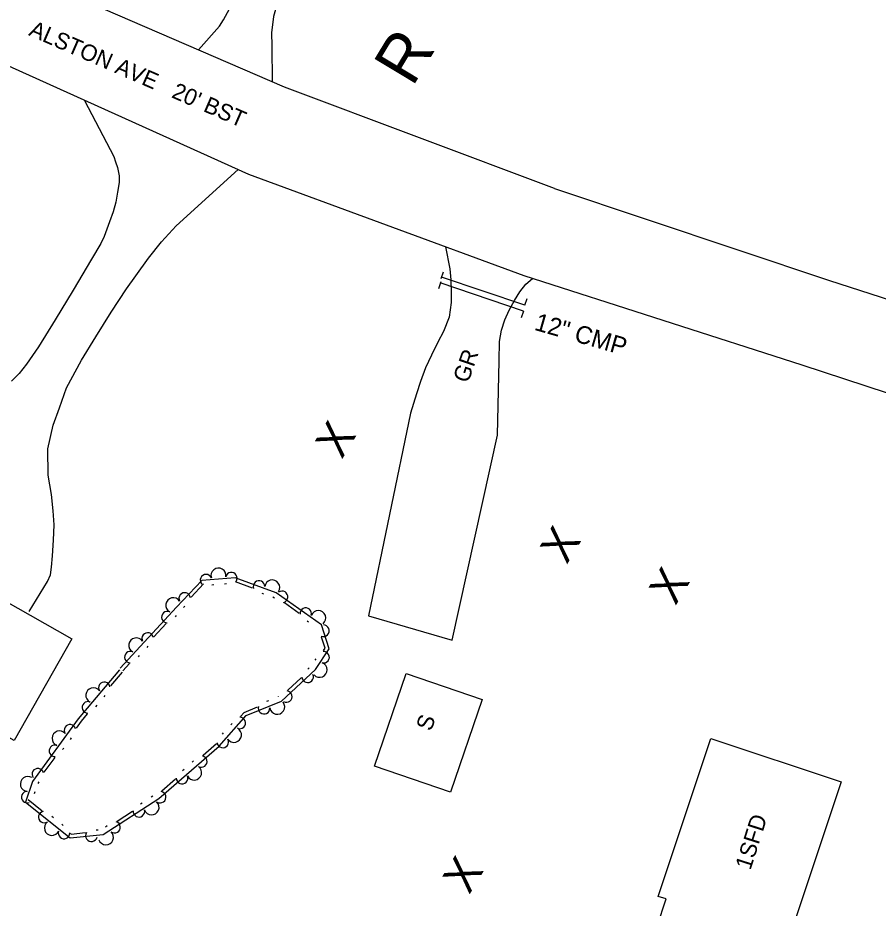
# Model space of a CAD drawing. Extents: x 2030130 to 2036320, y 723205 to 762423.
# Drawn here: x 2032711.6 to 2032905.6, y 760450.9 to 760651.9 of the extents above; entities that cross this region are included whole.
import ezdxf

# ---------------------------------------------------------------- set-up
doc = ezdxf.new("R2010")
doc.units = 0
for name, color, linetype in [('Draft_Station Cardinal Points', 7, 'Continuous'), ('Draft_Station Labels Major', 7, 'Continuous'), ('Draft_Station Tics Major', 7, 'Continuous'), ('Draft_Station Tics Minor', 7, 'Continuous'), ('Exist Terrain Model Ground Surface', 7, 'Continuous'), ('Old_Level_23', 7, 'Continuous'), ('Old_Level_26', 7, 'Continuous'), ('Old_Level_28', 7, 'Continuous')]:
    doc.layers.add(name, color=color, linetype=linetype)

msp = doc.modelspace()

# ---------------------------------------------------------------- linework, layer by layer
at = {"layer": 'Draft_Station Labels Major'}
for points in [[(2032752.34, 760644.62), (2032757.03, 760649.97), (2032757.96, 760651.43), (2032760.11, 760655.38), (2032761.37, 760659.07), (2032762.73, 760664.47), (2032770.18, 760709.31), (2032771.53, 760735.41)], [(2032780.04, 760733.35), (2032779.16, 760708.37), (2032776.48, 760684.96), (2032775.31, 760677.51), (2032774.46, 760672.51), (2032773.6, 760667.55), (2032772.54, 760662.87), (2032770.43, 760656.46), (2032769.22, 760652.17), (2032768.74, 760648.45), (2032768.83, 760645.51), (2032768.92, 760637.43)], [(2032832.59, 760613.36), (2032771.69, 760636.24), (2032711.99, 760662.1)], [(2032825.76, 760593.66), (2032763.66, 760616.53), (2032703.33, 760643.73), (2032699.59, 760645.59)], [(2032726.62, 760633.23), (2032733.21, 760620.6), (2032733.62, 760619.35), (2032734.05, 760618.08), (2032734.3, 760616.94), (2032734.41, 760616.17), (2032734.39, 760614.69), (2032734.07, 760612.53), (2032733.65, 760610.24), (2032733.06, 760608.08), (2032732.28, 760605.84), (2032731.02, 760602.53), (2032730.27, 760600.96), (2032728.2, 760597.39), (2032724.07, 760590.43), (2032719.97, 760583.71), (2032716.25, 760577.65), (2032713.53, 760573.73), (2032711.84, 760571.59), (2032710.16, 760569.86)], [(2032714.12, 760517.87), (2032718.27, 760524.7), (2032718.92, 760526.17), (2032719.16, 760527.93), (2032719.42, 760530.43), (2032719.62, 760534.02), (2032719.79, 760537.49), (2032719.55, 760540.64), (2032719.15, 760544.27), (2032718.4, 760548.66), (2032718.32, 760554.57), (2032719.55, 760559.95), (2032721, 760563.82), (2032722.56, 760568.39), (2032725.95, 760574.6), (2032729.13, 760579.86), (2032732.59, 760585.48), (2032736.08, 760590.7), (2032738.16, 760593.62), (2032741.04, 760597.62), (2032744, 760601.3), (2032747.3, 760604.91), (2032761.28, 760617.61)], [(2032832.59, 760613.36), (2032894.61, 760592.59), (2032957.05, 760572.43), (2033019.49, 760552.28)], [(2032808.03, 760600.19), (2032809, 760595.23), (2032809.25, 760592.75), (2032809.3, 760590.11), (2032809.33, 760587.59), (2032808.81, 760584.29), (2032807.53, 760581.09), (2032806.3, 760578.65), (2032804.83, 760575.77), (2032803.51, 760572.85), (2032802.39, 760569.78), (2032801.5, 760567), (2032800.15, 760562.67), (2032790.64, 760516.94), (2032809.54, 760511.46), (2032819.73, 760557.72), (2032820.12, 760574.49), (2032820.23, 760578.8), (2032820.67, 760581.4), (2032821.37, 760583.69), (2032822.35, 760585.87), (2032823.55, 760588.1), (2032824.78, 760590.03), (2032826.14, 760591.76), (2032827.6, 760593.07)], [(2033013.2, 760532.89), (2032950.76, 760553.04), (2032888.41, 760573.49), (2032825.76, 760593.66)]]:
    msp.add_lwpolyline(points, dxfattribs=at)
at = {"layer": 'Draft_Station Tics Major'}
for points in [[(2032734.47, 760504.77), (2032725.2, 760493.64), (2032714.87, 760479.52), (2032713.33, 760474.89), (2032723.35, 760466.83), (2032730.83, 760467.54), (2032743.34, 760475.72), (2032756.96, 760487.5), (2032763.08, 760494.42), (2032771.02, 760497.68), (2032778.68, 760504.78), (2032781.78, 760509.48), (2032780.04, 760514.92), (2032769.82, 760522.14), (2032760.55, 760525.5), (2032753.06, 760524.9), (2032747.34, 760518.87), (2032734.65, 760505.09)], [(2032753.47, 760524.14), (2032750.65, 760521.16)], [(2032755.75, 760523.88), (2032755.34, 760523.84)], [(2032758.62, 760524.11), (2032758.21, 760524.07)], [(2032764.52, 760523.19), (2032760.67, 760524.58)], [(2032767.08, 760521.82), (2032766.7, 760521.96)], [(2032769.44, 760520.9), (2032769.11, 760521.14)], [(2032749.25, 760519.1), (2032748.97, 760518.8)], [(2032775.04, 760517.45), (2032771.69, 760519.82)], [(2032745.06, 760515.18), (2032742.28, 760512.16)], [(2032747.31, 760517.01), (2032747.03, 760516.71)], [(2032777.14, 760515.46), (2032776.81, 760515.7)], [(2032780.52, 760509.06), (2032780.88, 760509.6), (2032780.07, 760512.14)], [(2032740.92, 760510.07), (2032740.64, 760509.77)], [(2032738.97, 760507.96), (2032738.69, 760507.66)], [(2032778.6, 760506.89), (2032778.82, 760507.23)], [(2032736.73, 760506.13), (2032735.26, 760504.53)], [(2032776.99, 760504.89), (2032777.29, 760505.17)], [(2032735.1, 760504.24), (2032732.47, 760501.09)], [(2032772.46, 760500.14), (2032775.47, 760502.92)], [(2032731.21, 760498.94), (2032730.95, 760498.62)], [(2032767.76, 760497.67), (2032768.14, 760497.83)], [(2032770.34, 760498.73), (2032770.38, 760498.76)], [(2032729.38, 760496.73), (2032729.12, 760496.42)], [(2032761.81, 760494.22), (2032762.59, 760495.11), (2032765.64, 760496.36)], [(2032727.23, 760494.79), (2032725.85, 760493.13), (2032724.73, 760491.6)], [(2032759.6, 760492.34), (2032759.87, 760492.65)], [(2032723.61, 760489.37), (2032723.37, 760489.04)], [(2032757.7, 760490.19), (2032757.97, 760490.5)], [(2032721.91, 760487.06), (2032721.67, 760486.73)], [(2032753.35, 760485.47), (2032756.38, 760488.09)], [(2032719.89, 760484.98), (2032717.46, 760481.67)], [(2032750.91, 760483.9), (2032751.22, 760484.17)], [(2032748.74, 760482.02), (2032749.05, 760482.29)], [(2032716.34, 760479.44), (2032716.1, 760479.11)], [(2032744.04, 760477.42), (2032747.15, 760480.1)], [(2032715.39, 760477.17), (2032715.26, 760476.78)], [(2032713.89, 760475.49), (2032717.09, 760472.92)], [(2032741.64, 760476.08), (2032741.98, 760476.31)], [(2032739.24, 760474.51), (2032739.58, 760474.73)], [(2032719.26, 760471.7), (2032719.58, 760471.44)], [(2032733.97, 760470.57), (2032737.4, 760472.82)], [(2032721.49, 760469.9), (2032721.81, 760469.64)], [(2032731.34, 760469.34), (2032731.69, 760469.57)], [(2032723.47, 760467.78), (2032723.6, 760467.68), (2032726.86, 760467.99)], [(2032729.27, 760468.63), (2032729.68, 760468.66)]]:
    msp.add_lwpolyline(points, dxfattribs=at)
for centre, radius, start, end in [((2032756.82, 760526.02), 1.69, 350.5307, 198.6032), ((2032754.02, 760524.97), 1.3, 23.0019, 223.7985), ((2032759.74, 760525.43), 1.3, 325.3354, 166.132), ((2032765.96, 760523.54), 1.3, 358.5358, 199.3323), ((2032768.94, 760523.33), 1.69, 326.0646, 174.1371), ((2032749.21, 760520.84), 1.3, 7.2968, 208.0933), ((2032771.16, 760521.2), 1.3, 285.515, 126.3115), ((2032746.63, 760519.31), 1.69, 33.3291, 241.4016), ((2032745.29, 760516.64), 1.3, 65.8003, 266.5969), ((2032776.51, 760517.41), 1.3, 343.1814, 183.978), ((2032779.33, 760516.42), 1.69, 310.7103, 158.7827), ((2032740.85, 760511.81), 1.3, 8.1338, 208.9304), ((2032780.47, 760513.56), 1.3, 248.4828, 89.2793), ((2032738.3, 760510.26), 1.69, 33.3291, 241.4016), ((2032736.96, 760507.59), 1.3, 65.8003, 266.5969), ((2032780.53, 760507.58), 1.3, 255.0228, 95.8194), ((2032779.63, 760504.73), 1.69, 222.5516, 70.6241), ((2032776.93, 760503.16), 1.3, 183.5829, 24.3794), ((2032731.06, 760500.67), 1.3, 11.0049, 211.8014), ((2032728.59, 760498.99), 1.69, 36.2001, 244.2726), ((2032772.12, 760498.7), 1.3, 241.2493, 82.0459), ((2032727.38, 760496.26), 1.3, 68.6713, 269.4679), ((2032770.06, 760496.4), 1.69, 188.2658, 36.3383), ((2032767.09, 760496.07), 1.3, 163.0705, 3.8671), ((2032761.61, 760492.75), 1.3, 246.9458, 87.7424), ((2032723.34, 760491.09), 1.3, 14.5724, 215.369), ((2032760.32, 760490.06), 1.69, 214.4746, 62.5471), ((2032720.98, 760489.26), 1.69, 39.7677, 247.8402), ((2032757.8, 760488.45), 1.3, 189.2793, 30.0759), ((2032719.95, 760486.46), 1.3, 72.2389, 273.0355), ((2032752.96, 760484.04), 1.3, 239.2811, 80.0777), ((2032716.08, 760481.16), 1.3, 14.5724, 215.369), ((2032751.32, 760481.54), 1.69, 206.8099, 54.8824), ((2032713.83, 760478.99), 1.69, 57.5775, 265.65), ((2032748.61, 760480.29), 1.3, 181.6146, 22.4112), ((2032713.7, 760476.01), 1.3, 90.0487, 290.8453), ((2032743.65, 760475.99), 1.3, 239.2811, 80.0777), ((2032741.73, 760473.69), 1.69, 199.1672, 47.2397), ((2032738.88, 760472.81), 1.3, 173.9719, 14.7685), ((2032717.53, 760471.51), 1.3, 101.9397, 302.7363), ((2032719.25, 760469.07), 1.69, 127.135, 335.2075), ((2032733.39, 760469.21), 1.3, 231.6384, 72.4349), ((2032722, 760467.91), 1.3, 159.6062, 0.4027), ((2032728.16, 760467.28), 1.3, 146.186, 346.9826), ((2032731.44, 760466.95), 1.69, 199.1672, 47.2397)]:
    msp.add_arc(centre, radius, start, end, dxfattribs=at)
at = {"layer": 'Draft_Station Tics Minor'}
for p, q in [((2032807.05, 760593.02), (2032807.58, 760594.58)), ((2032806.99, 760592.29), (2032806.47, 760590.74)), ((2032825.9, 760587.01), (2032826.43, 760588.56)), ((2032825.59, 760585.7), (2032825.06, 760584.14))]:
    msp.add_line(p, q, dxfattribs=at)
for points in [[(2032825.59, 760585.7), (2032806.81, 760592.05)], [(2032825.9, 760587.01), (2032807.13, 760593.36)]]:
    msp.add_lwpolyline(points, dxfattribs=at)
at = {"layer": 'Exist Terrain Model Ground Surface'}
for points in [[(2032696.03, 760527.43), (2032723.77, 760511.74), (2032710.77, 760488.76), (2032683.03, 760504.45)], [(2032816.3, 760498.04), (2032809.18, 760477.13), (2032791.99, 760482.98), (2032799.11, 760503.89)], [(2032856, 760453.62), (2032867.86, 760489.25), (2032897.22, 760479.47), (2032885.35, 760443.79), (2032882.42, 760444.77), (2032880.41, 760438.71), (2032855.74, 760446.91), (2032857.78, 760453.03)]]:
    msp.add_lwpolyline(points, close=True, dxfattribs=at)

# ---------------------------------------------------------------- texts
at = {"layer": 'Draft_Station Cardinal Points'}
msp.add_text('R', height=10.66, rotation=58.9267, dxfattribs=at).set_placement((2032800.56, 760636.09))
at = {"layer": 'Draft_Station Tics Major'}
for p in [(2032784.62, 760552.1), (2032835.34, 760528.36), (2032859.86, 760519.07), (2032813.35, 760453.86)]:
    msp.add_text('X', height=7.38, rotation=58.9267, dxfattribs=at).set_placement(p)
at = {"layer": 'Old_Level_23'}
for s, height, rotation, p in [("ALSTON AVE   20' BST", 3.6909, 336.4783, (2032713.83, 760647.99)), ('GR', 3.691, 70.9971, (2032813.11, 760569.28))]:
    msp.add_text(s, height=height, rotation=rotation, dxfattribs=at).set_placement(p)
at = {"layer": 'Old_Level_26'}
msp.add_text('12" CMP', height=4, rotation=343.9546, dxfattribs=at).set_placement((2032827.85, 760581.49))
at = {"layer": 'Old_Level_28'}
for s, height, rotation, p in [('S', 3.69, 71.2023, (2032804.78, 760490.72)), ('1SFD', 3.691, 72.2658, (2032876.78, 760459.39))]:
    msp.add_text(s, height=height, rotation=rotation, dxfattribs=at).set_placement(p)

doc.saveas('drawing.dxf')
